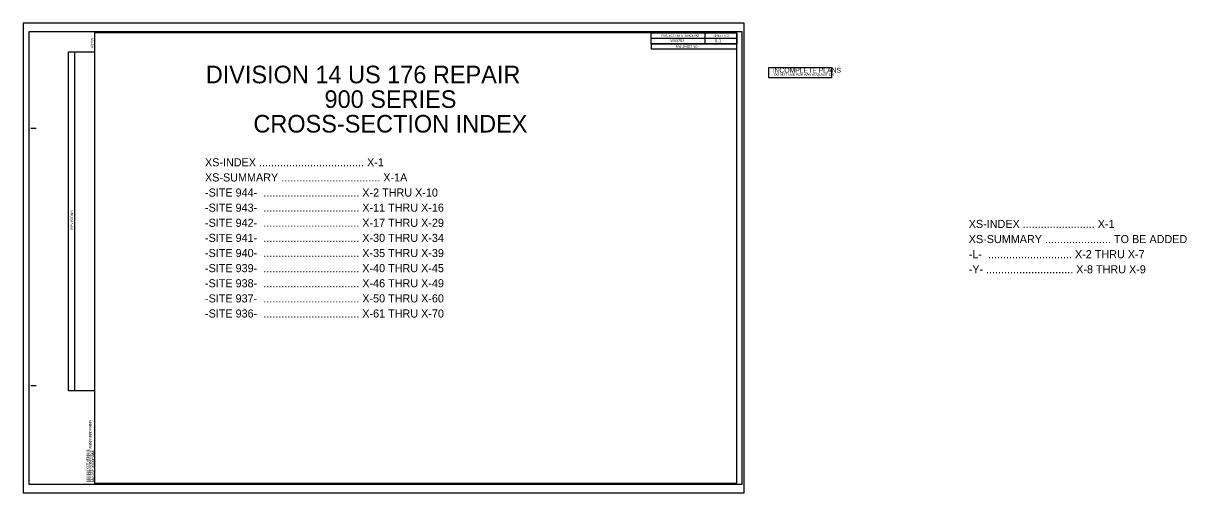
# Model space of a CAD drawing. Extents: x -5 to 538, y 254 to 473.
import ezdxf

# ---------------------------------------------------------------- set-up
doc = ezdxf.new("R2010")
doc.units = 0
for name, color, linetype in [('Prop DSN Text', 7, 'Continuous'), ('Prop XS Project Number', 7, 'Continuous'), ('Sheet Block Revision CELL', 7, 'Continuous'), ('Sheet Cutting Line CELL', 7, 'Continuous'), ('Sheet Data Field CELL', 7, 'Continuous'), ('Sheet Plan CELL', 7, 'Continuous'), ('Sheet Plot Border Inside CELL', 7, 'Continuous'), ('Sheet Plot Border Outside CELL', 7, 'Continuous'), ('Sheet Sticker Incomplete CELL', 7, 'Continuous')]:
    doc.layers.add(name, color=color, linetype=linetype)

msp = doc.modelspace()

# ---------------------------------------------------------------- linework, layer by layer
at = {"layer": 'Sheet Block Revision CELL'}
msp.add_line((19.24, 301.35), (19.24, 459.48), dxfattribs=at)
msp.add_lwpolyline([(16.33, 301.35), (16.33, 459.48), (28.44, 459.48), (28.44, 301.35)], close=True, dxfattribs=at)
at = {"layer": 'Sheet Cutting Line CELL'}
for p, q in [((331.84, 472.85), (-4.86, 472.85)), ((-4.86, 472.85), (-4.86, 253.85)), ((-4.86, 253.85), (331.84, 253.85))]:
    msp.add_line(p, q, dxfattribs=at)
at = {"layer": 'Sheet Plan CELL'}
for p, q in [((28.44, 468.35), (28.44, 468.35)), ((313.43, 468.34), (313.44, 463.34)), ((288.43, 465.84), (328.44, 465.84)), ((288.43, 463.34), (328.44, 463.34)), ((288.43, 463.34), (328.44, 463.34)), ((288.43, 463.34), (288.43, 460.84)), ((328.44, 460.84), (288.43, 460.84)), ((-1.26, 423.85), (1.24, 423.85)), ((-1.26, 303.85), (1.24, 303.85)), ((28.44, 258.35), (28.44, 258.35))]:
    msp.add_line(p, q, dxfattribs=at)
for points in [[(328.45, 468.35), (28.44, 468.35), (28.44, 258.35), (328.44, 258.35)], [(288.43, 468.35), (328.45, 468.35), (328.44, 463.34), (288.43, 463.34)]]:
    msp.add_lwpolyline(points, close=True, dxfattribs=at)
at = {"layer": 'Sheet Plot Border Inside CELL'}
msp.add_lwpolyline([(-2.26, 257.85), (330.94, 257.85), (330.94, 468.85), (-2.26, 468.85)], close=True, dxfattribs=at)
at = {"layer": 'Sheet Plot Border Outside CELL'}
msp.add_lwpolyline([(-4.86, 253.85), (331.84, 253.85), (331.84, 472.85), (-4.86, 472.85)], close=True, dxfattribs=at)
at = {"layer": 'Sheet Sticker Incomplete CELL'}
msp.add_lwpolyline([(343.26, 447.45), (343.26, 452.15), (372.66, 452.15), (372.66, 447.45)], close=True, dxfattribs=at)

# ---------------------------------------------------------------- texts
at = {"layer": 'Prop DSN Text'}
for s, height, p in [('DIVISION 14 US 176 REPAIR', 8.2021, (80.37, 444.86)), ('900 SERIES', 8.202, (135.84, 433.37)), ('CROSS-SECTION INDEX', 8.2021, (102.61, 421.89)), ('XS-INDEX ................................... X-1', 3.773, (80, 406.11)), ('XS-SUMMARY ................................. X-1A', 3.773, (80, 399.05)), ('-SITE 944-  ................................ X-2 THRU X-10', 3.773, (80, 392)), ('-SITE 943-  ................................ X-11 THRU X-16', 3.773, (80, 384.95)), ('-SITE 942-  ................................ X-17 THRU X-29', 3.773, (80, 377.89)), ('XS-INDEX ........................ X-1', 3.773, (436.67, 377.36)), ('-SITE 941-  ................................ X-30 THRU X-34', 3.773, (80, 370.84)), ('XS-SUMMARY ...................... TO BE ADDED', 3.773, (436.67, 370.3)), ('-SITE 940-  ................................ X-35 THRU X-39', 3.773, (80, 363.78)), ('-L-  ............................ X-2 THRU X-7', 3.773, (436.67, 363.25)), ('-SITE 939-  ................................ X-40 THRU X-45', 3.773, (80, 356.73)), ('-Y- ............................. X-8 THRU X-9', 3.773, (436.67, 356.19)), ('-SITE 938-  ................................ X-46 THRU X-49', 3.773, (80, 349.68)), ('-SITE 937-  ................................ X-50 THRU X-60 ', 3.773, (80, 342.62)), ('-SITE 936-  ................................ X-61 THRU X-70 ', 3.773, (80, 335.57))]:
    msp.add_text(s, height=height, dxfattribs=at).set_placement(p)
at = {"layer": 'Prop XS Project Number'}
msp.add_text('W03293', height=1.26, dxfattribs=at).set_placement((297.37, 464.05))
at = {"layer": 'Sheet Block Revision CELL'}
msp.add_text('REVISIONS', height=1.2, rotation=90, dxfattribs=at).set_placement((18.43, 376.58))
at = {"layer": 'Sheet Data Field CELL'}
msp.add_text('   X-1   ', height=1.5, rotation=0, dxfattribs=at).set_placement((316.23, 463.9))
at = {"layer": 'Sheet Plan CELL'}
for s, height, rotation, p in [('PROJECT REFERENCE NO.', 1, 0, (292.87, 466.61)), ('SHEET NO.', 1, 0, (317.5, 466.59)), ('8/17/99', 1.05, 90, (27.79, 461.31)), ('R/W SHEET NO.', 1, 0, (299.83, 461.5)), ('$$$$$$$$$$$$$$$$DGN$$$$$$$$$$$$$$$$', 1.05, 90, (26.91, 258.82)), ('$$$$$$SYSTIME$$$$$', 1.05, 90, (25.7, 258.82)), ('$$$$USERNAME$$$$', 1.05, 90, (28.22, 258.83))]:
    msp.add_text(s, height=height, rotation=rotation, dxfattribs=at).set_placement(p)
at = {"layer": 'Sheet Sticker Incomplete CELL'}
for s, height, p in [('INCOMPLETE PLANS', 2.304, (345.05, 449.79)), ('DO NOT USE FOR R/W ACQUISITION', 1.152, (345.7, 448.4))]:
    msp.add_text(s, height=height, dxfattribs=at).set_placement(p)

doc.saveas('drawing.dxf')
